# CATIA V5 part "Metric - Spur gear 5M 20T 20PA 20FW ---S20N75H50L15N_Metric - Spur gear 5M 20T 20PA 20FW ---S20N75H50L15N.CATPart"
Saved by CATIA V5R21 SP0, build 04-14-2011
Part number: Metric - Spur gear 5M 20T 20PA 20FW ---S20N75H50L15N_Metric - Spur gear 5M 20T 20PA 20FW ---S20N75H50L15N
Revision: ANY
Definition: UNKNOWN
Nomenclature: Metric - Spur gear 5M 20T 20PA 20FW ---S20N75H50L15N_Metric - Spur gear 5M 20T 20PA 20FW ---S20N75H50L15N
Source: Unknown
Material "Light Green": density 7860 kg/m3, Young's modulus 2e+11 Pa, Poisson ratio 0.266
Bounding box of the stored display mesh (mm): x 0 to 20, y -54.516 to 54.516, z -54.516 to 54.516
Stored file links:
  F:\catia world\MY WORK\rack and pinion\Metric - Spur gear 5M 20T 20PA 20FW ---S20N75H50L15N_Metric - Spur gear 5M 20T 20PA 20FW ---S20N75H50L15N.CATPart
  C:\Program Files\Dassault Systemes\B21\intel_a\startup\materials\red_env_512x512.jpg
  C:\Program Files\Dassault Systemes\B21\intel_a\startup\materials\yellow_env_512x512.jpg
  C:\Program Files\Dassault Systemes\B21\intel_a\startup\materials\blue_env_512x512.jpg
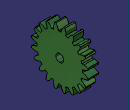
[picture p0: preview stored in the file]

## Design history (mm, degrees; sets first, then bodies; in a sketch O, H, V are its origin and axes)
Set1
  Sketch1 on face of Solid1, origin (0, 0, 0), H (0, -1, 0), V (0, 0, 1)
    circle A1 centre (0, 0) radius 49.3745
    reference projected arc E1 centre (0, 0) radius 43.749 from (11.1535, -42.3034) to (15.8419, -40.78) ccw from edge [face of Solid1 | face of Solid1]
    radius A1 = 49.3745
    concentricity: A1 E1
Body1 "Bore" (main body), material "Light Green"
  Solid1: solid without history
